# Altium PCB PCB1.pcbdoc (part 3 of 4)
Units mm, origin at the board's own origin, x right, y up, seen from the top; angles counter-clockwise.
Board outline 94.87 x 122.94 mm, 4 copper layers (Top Layer, Inner1, Inner2, Bottom Layer); 129 components, 127 nets, 713 pads, 345 vias.
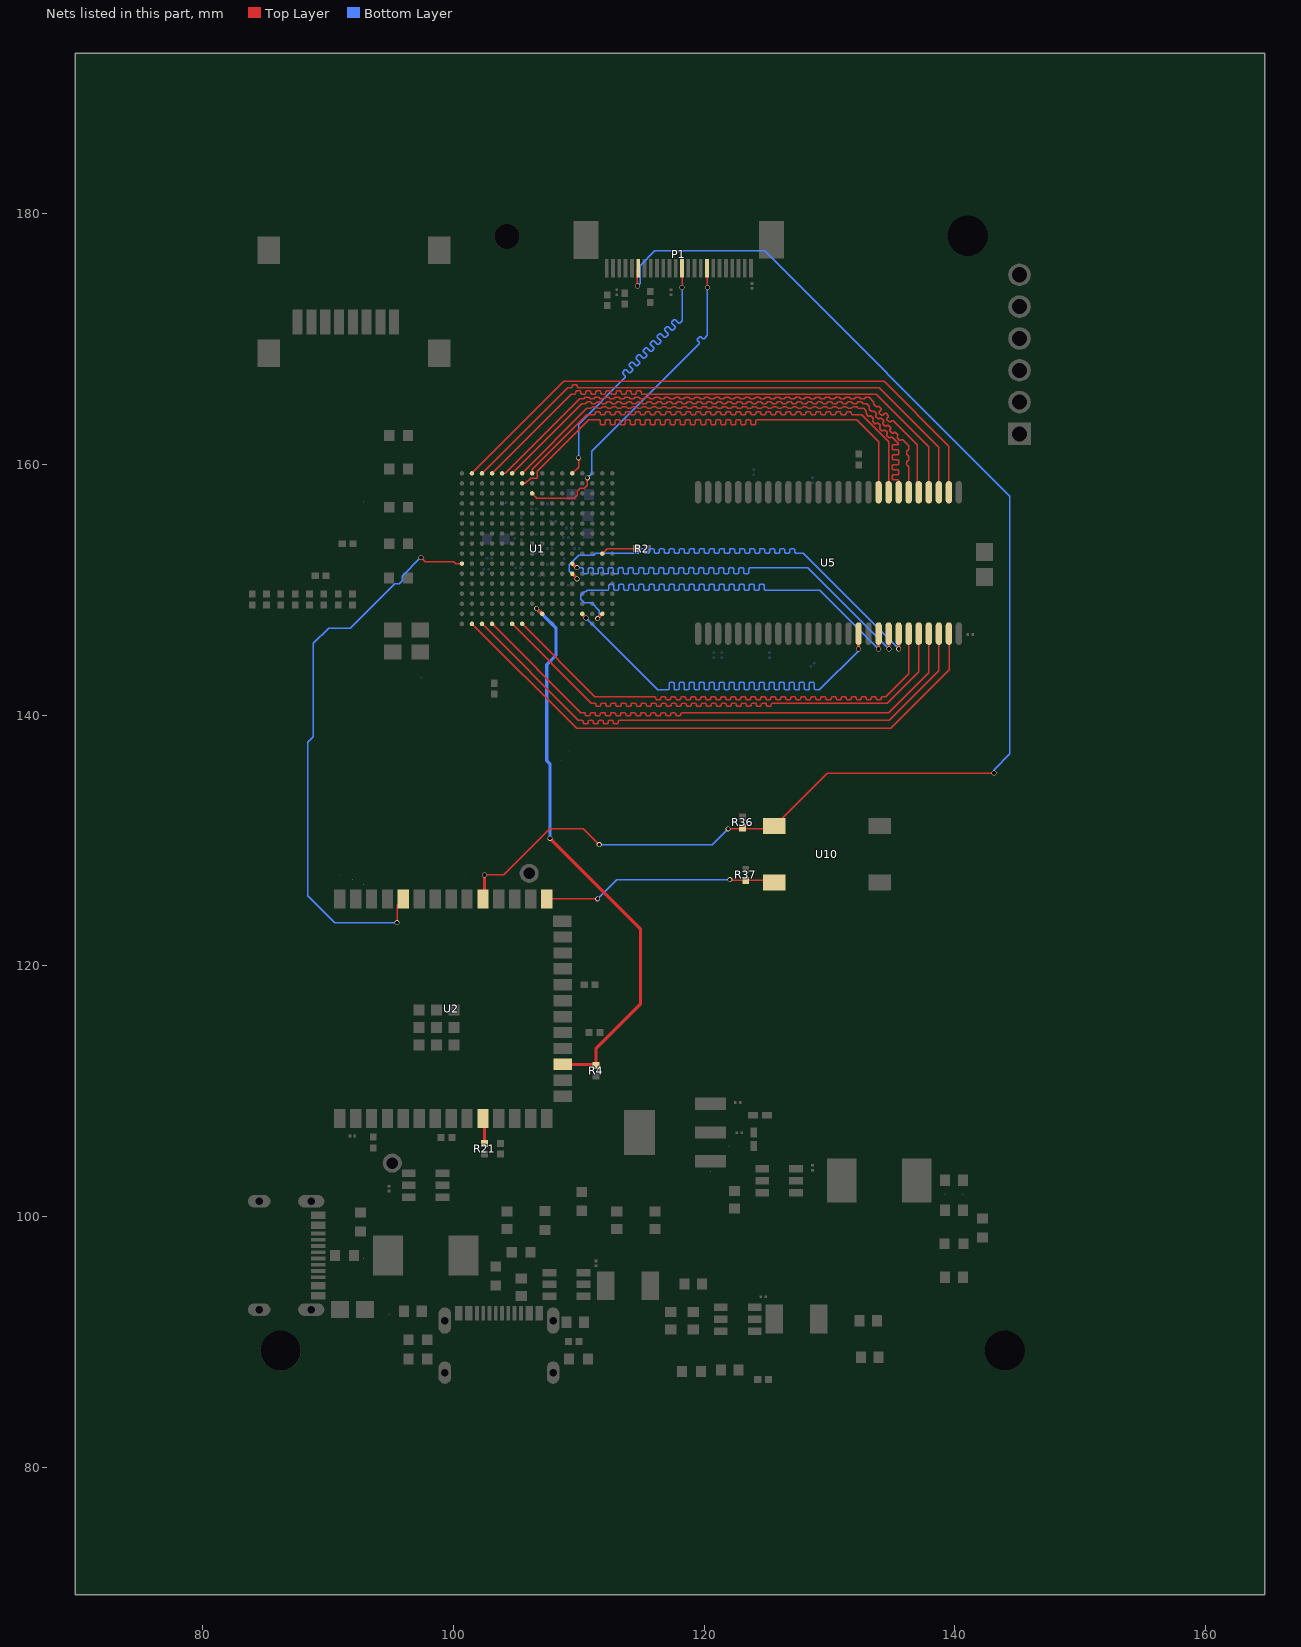
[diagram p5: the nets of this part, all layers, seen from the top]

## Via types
v1: diameter 0.4, hole 0.3, Top Layer to Bottom Layer, 308 vias
v2: diameter 1, hole 0.5, Top Layer to Bottom Layer, 35 vias
v3: diameter 0.5, hole 0.3, Top Layer to Bottom Layer, 2 vias

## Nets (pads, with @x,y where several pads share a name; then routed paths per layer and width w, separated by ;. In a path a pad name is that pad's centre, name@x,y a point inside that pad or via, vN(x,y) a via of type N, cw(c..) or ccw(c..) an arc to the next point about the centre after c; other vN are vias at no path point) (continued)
MCLK: P1.13 U1.A12 | length 27.1
  Top Layer w0.1: U1.A12@109.48,159.289 109.982,159.791 v1(109.982,160.528) ; v1(118.237,174.117) P1.13@118.237,175.655
  Bottom Layer w0.1: v1(109.982,160.528) 109.982,163.195 113.727,166.94 113.727,167.04 113.496,167.271 113.496,167.371 113.679,167.554 113.779,167.554 114.01,167.323 114.11,167.323 114.293,167.506 114.293,167.606 114.012,167.887 114.012,167.987 114.195,168.17 114.295,168.17 114.576,167.889 114.676,167.889 114.858,168.071 114.858,168.171 114.577,168.452 114.577,168.552 114.76,168.735 114.86,168.735 115.141,168.454 115.241,168.454 115.424,168.637 115.424,168.737 115.143,169.018 115.143,169.118 115.326,169.301 115.426,169.301 115.707,169.02 115.807,169.02 115.99,169.203 115.99,169.303 115.709,169.584 115.709,169.684 115.892,169.867 115.992,169.867 116.273,169.586 116.373,169.586 116.555,169.768 116.555,169.868 116.274,170.149 116.274,170.249 116.457,170.432 116.557,170.432 116.838,170.151 116.938,170.151 117.121,170.334 117.121,170.434 116.84,170.715 116.84,170.815 117.023,170.998 117.123,170.998 117.404,170.717 117.504,170.717 117.687,170.9 117.687,171 117.406,171.281 117.406,171.381 117.589,171.564 117.689,171.564 117.97,171.283 118.07,171.283 118.237,171.45 v1(118.237,174.117)
PCLK: P1.17 U1.C8 | length 27
  Top Layer w0.1: U1.C8@106.28,157.689 106.662,157.307 109.638,157.307 109.862,157.531 109.862,157.847 110.122,158.107 110.438,158.107 110.662,158.331 110.662,158.647 110.68,158.665 v1(110.68,158.937) ; P1.17@120.237,175.656 120.269,175.624 v1(120.269,174.117)
  Bottom Layer w0.1: v1(110.68,158.937) 111.019,159.276 111.019,161.057 119.609,169.647 119.609,169.747 119.455,169.901 119.455,170.001 119.637,170.183 119.737,170.183 119.891,170.029 119.991,170.029 120.269,170.307 v1(120.269,174.117)
PROGRAM: R37.1 U2.27 U10.3 | length 18.9
  Top Layer w0.1: U2.27@107.437,125.336 111.493,125.336 v1(111.506,125.349) ; v1(122.047,126.873) 122.099,126.821 R37.1@123.317,126.821 125.428,126.821 U10.3@125.594,126.655
  Bottom Layer w0.1: v1(111.506,125.349) 113.03,126.873 v1(122.047,126.873)
PROGRAMN: pad.55@107.442,136.377 R4.2 U1.R9 U2.17 | length 45.1
  Top Layer w0.254: v1(106.643,148.5) 106.669,148.5 U1.R9@107.08,148.089 ; v1(107.696,130.175) 114.935,122.936 114.935,116.984 111.379,113.428 R4.2@111.379,112.066 111.304,112.141 U2.17@108.844,112.141
  Bottom Layer w0.254: v1(106.643,148.5) 108.175,146.968 108.175,144.758 107.442,144.025 pad.55@107.442,136.377 107.696,136.123 v1(107.696,130.175)
RESET: P1.6 R36.1 U2.31 U10.1 | length 110.8
  Top Layer w0.1: v1(102.484,127.254) 104.013,127.254 107.696,130.937 110.363,130.937 v1(111.633,129.667) ; v1(114.681,174.244) 114.681,175.599 P1.6@114.738,175.655 ; v1(121.92,130.937) 125.376,130.937 U10.1@125.594,131.155 129.821,135.382 v1(143.129,135.382)
  Top Layer w0.254: U2.31@102.484,125.336 v1(102.484,127.254)
  Bottom Layer w0.1: v1(111.633,129.667) 120.65,129.667 v1(121.92,130.937) ; v1(114.681,174.244) 114.907,174.47 114.907,175.867 116.078,177.038 124.841,177.038 144.399,157.48 144.399,136.906 143.129,135.636 v1(143.129,135.382)
RX: U1.K1 U2.36 | length 45.5
  Top Layer w0.1: v1(95.504,123.444) 95.504,124.833 U2.36@96.007,125.336 ; v1(97.41,152.582) 97.738,152.254 100.037,152.254 100.202,152.089 U1.K1@100.68,152.089
  Bottom Layer w0.1: v1(95.504,123.444) 90.551,123.444 88.392,125.603 88.392,137.831 88.832,138.271 88.832,145.728 90.043,146.939 91.767,146.939 95.302,150.474 95.671,150.474 95.906,150.709 95.906,151.078 v1(97.41,152.582)
SCL: R21.1 U2.10 | length 1.9
  Top Layer w0.254: U2.10@102.484,107.836 102.489,107.831 R21.1@102.489,105.918
SD_A0: U1.T6 U5.23 | length 45.3
  Top Layer w0.1: U1.T6@104.68,147.289 110.999,140.97 111.299,140.97 111.37,140.899 111.37,140.787 111.44,140.716 111.699,140.716 111.77,140.787 111.77,140.899 111.84,140.97 112.099,140.97 112.17,140.899 112.17,140.787 112.24,140.716 112.499,140.716 112.57,140.787 112.57,140.899 112.64,140.97 112.899,140.97 112.97,140.899 112.97,140.787 113.04,140.716 113.299,140.716 113.37,140.787 113.37,140.899 113.44,140.97 113.699,140.97 113.77,140.899 113.77,140.787 113.84,140.716 114.099,140.716 114.17,140.787 114.17,140.899 114.24,140.97 114.499,140.97 114.57,140.899 114.57,140.787 114.64,140.716 114.899,140.716 114.97,140.787 114.97,140.899 115.04,140.97 115.299,140.97 115.37,140.899 115.37,140.787 115.44,140.716 115.699,140.716 115.77,140.787 115.77,140.899 115.84,140.97 116.099,140.97 116.17,140.899 116.17,140.787 116.24,140.716 116.499,140.716 116.57,140.787 116.57,140.899 116.64,140.97 116.899,140.97 116.97,140.899 116.97,140.787 117.04,140.716 117.299,140.716 117.37,140.787 117.37,140.899 117.44,140.97 117.699,140.97 117.77,140.899 117.77,140.787 117.84,140.716 118.099,140.716 118.17,140.787 118.17,140.899 118.24,140.97 118.499,140.97 118.57,140.899 118.57,140.787 118.64,140.716 118.899,140.716 118.97,140.787 118.97,140.899 119.04,140.97 119.299,140.97 119.37,140.899 119.37,140.787 119.44,140.716 119.699,140.716 119.77,140.787 119.77,140.899 119.84,140.97 120.099,140.97 120.17,140.899 120.17,140.787 120.24,140.716 120.499,140.716 120.57,140.787 120.57,140.899 120.64,140.97 120.899,140.97 120.97,140.899 120.97,140.787 121.04,140.716 121.299,140.716 121.37,140.787 121.37,140.899 121.44,140.97 121.699,140.97 121.77,140.899 121.77,140.787 121.84,140.716 122.099,140.716 122.17,140.787 122.17,140.899 122.24,140.97 122.499,140.97 122.57,140.899 122.57,140.787 122.64,140.716 122.899,140.716 122.97,140.787 122.97,140.899 123.04,140.97 123.299,140.97 123.37,140.899 123.37,140.787 123.44,140.716 123.699,140.716 123.77,140.787 123.77,140.899 123.84,140.97 124.099,140.97 124.17,140.899 124.17,140.787 124.24,140.716 124.499,140.716 124.57,140.787 124.57,140.899 124.64,140.97 124.899,140.97 124.97,140.899 124.97,140.787 125.04,140.716 125.299,140.716 125.37,140.787 125.37,140.899 125.44,140.97 134.62,140.97 137.121,143.471 U5.23@137.121,146.504
SD_A1: U1.T4 U5.24 | length 45.6
  Top Layer w0.1: U1.T4@103.08,147.289 110.161,140.208 110.461,140.208 110.532,140.137 110.532,140.025 110.602,139.954 110.861,139.954 110.932,140.025 110.932,140.137 111.002,140.208 111.261,140.208 111.332,140.137 111.332,140.025 111.402,139.954 111.661,139.954 111.732,140.025 111.732,140.137 111.802,140.208 112.061,140.208 112.132,140.137 112.132,140.025 112.202,139.954 112.461,139.954 112.532,140.025 112.532,140.137 112.602,140.208 112.861,140.208 112.932,140.137 112.932,140.025 113.002,139.954 113.261,139.954 113.332,140.025 113.332,140.137 113.402,140.208 113.661,140.208 113.732,140.137 113.732,140.025 113.802,139.954 114.061,139.954 114.132,140.025 114.132,140.137 114.202,140.208 114.461,140.208 114.532,140.137 114.532,140.025 114.602,139.954 114.861,139.954 114.932,140.025 114.932,140.137 115.002,140.208 115.261,140.208 115.332,140.137 115.332,140.025 115.402,139.954 115.661,139.954 115.732,140.025 115.732,140.137 115.802,140.208 116.061,140.208 116.132,140.137 116.132,140.025 116.202,139.954 116.461,139.954 116.532,140.025 116.532,140.137 116.602,140.208 116.861,140.208 116.932,140.137 116.932,140.025 117.002,139.954 117.261,139.954 117.332,140.025 117.332,140.137 117.402,140.208 117.661,140.208 117.732,140.137 117.732,140.025 117.802,139.954 118.061,139.954 118.132,140.025 118.132,140.137 118.202,140.208 134.747,140.208 137.922,143.383 U5.24@137.922,146.503
SD_A2: U1.T3 U5.25 | length 45.9
  Top Layer w0.1: U1.T3@102.28,147.289 109.959,139.61 110.282,139.61 110.353,139.539 110.353,139.39 110.423,139.319 110.682,139.319 110.753,139.39 110.753,139.539 110.823,139.61 111.082,139.61 111.153,139.539 111.153,139.39 111.223,139.319 111.482,139.319 111.553,139.39 111.553,139.539 111.623,139.61 111.882,139.61 111.953,139.539 111.953,139.39 112.023,139.319 112.282,139.319 112.353,139.39 112.353,139.539 112.423,139.61 112.682,139.61 112.753,139.539 112.753,139.39 112.823,139.319 113.082,139.319 113.153,139.39 113.153,139.539 113.223,139.61 134.784,139.61 138.721,143.547 U5.25@138.721,146.504
SD_A3: U1.T2 U5.26 | length 46.4
  Top Layer w0.1: U1.T2@101.48,147.289 109.831,138.938 134.874,138.938 139.573,143.637 139.573,146.452 U5.26@139.521,146.504
SD_A4: U1.A2 U5.29 | length 46.9
  Top Layer w0.1: U1.A2@101.48,159.289 108.815,166.624 134.366,166.624 139.521,161.469 U5.29@139.521,157.788
SD_A5: U1.A3 U5.30 | length 45.2
  Top Layer w0.1: U1.A3@102.28,159.289 109.107,166.116 109.407,166.116 109.478,166.187 109.478,166.299 109.548,166.37 109.807,166.37 109.878,166.299 109.878,166.187 109.948,166.116 133.985,166.116 138.721,161.38 U5.30@138.721,157.788
SD_A6: U1.A4 U5.31 | length 45.2
  Top Layer w0.1: U1.A4@103.08,159.289 109.399,165.608 109.699,165.608 109.77,165.679 109.77,165.791 109.84,165.862 110.099,165.862 110.17,165.791 110.17,165.679 110.24,165.608 110.499,165.608 110.57,165.679 110.57,165.791 110.64,165.862 110.899,165.862 110.97,165.791 110.97,165.679 111.04,165.608 111.299,165.608 111.37,165.679 111.37,165.791 111.44,165.862 111.699,165.862 111.77,165.791 111.77,165.679 111.84,165.608 112.099,165.608 112.17,165.679 112.17,165.791 112.24,165.862 112.499,165.862 112.57,165.791 112.57,165.679 112.64,165.608 112.899,165.608 112.97,165.679 112.97,165.791 113.04,165.862 113.299,165.862 113.37,165.791 113.37,165.679 113.44,165.608 113.699,165.608 113.77,165.679 113.77,165.791 113.84,165.862 114.099,165.862 114.17,165.791 114.17,165.679 114.24,165.608 114.499,165.608 114.57,165.679 114.57,165.791 114.64,165.862 114.899,165.862 114.97,165.791 114.97,165.679 115.04,165.608 133.731,165.608 137.921,161.418 U5.31@137.921,157.788
SD_A7: U1.A5 U5.32 | length 45.1
  Top Layer w0.1: U1.A5@103.88,159.289 104.14,159.289 110.078,165.227 110.378,165.227 110.505,165.354 110.778,165.354 110.905,165.227 111.178,165.227 111.305,165.354 111.578,165.354 111.705,165.227 111.978,165.227 112.105,165.354 112.378,165.354 112.505,165.227 112.778,165.227 112.905,165.354 113.178,165.354 113.305,165.227 113.578,165.227 113.705,165.354 113.978,165.354 114.105,165.227 114.378,165.227 114.505,165.354 114.778,165.354 114.905,165.227 115.178,165.227 115.305,165.354 115.578,165.354 115.705,165.227 115.978,165.227 116.105,165.354 116.378,165.354 116.505,165.227 116.778,165.227 116.905,165.354 117.178,165.354 117.305,165.227 117.578,165.227 117.705,165.354 117.978,165.354 118.105,165.227 118.378,165.227 118.505,165.354 118.778,165.354 118.905,165.227 119.178,165.227 119.305,165.354 119.578,165.354 119.705,165.227 119.978,165.227 120.105,165.354 120.378,165.354 120.505,165.227 120.778,165.227 120.905,165.354 121.178,165.354 121.305,165.227 121.578,165.227 121.705,165.354 121.978,165.354 122.105,165.227 122.378,165.227 122.505,165.354 122.778,165.354 122.905,165.227 123.178,165.227 123.305,165.354 123.578,165.354 123.705,165.227 123.978,165.227 124.105,165.354 124.378,165.354 124.505,165.227 124.778,165.227 124.905,165.354 125.178,165.354 125.305,165.227 125.578,165.227 125.705,165.354 125.978,165.354 126.105,165.227 126.378,165.227 126.505,165.354 126.778,165.354 126.905,165.227 127.178,165.227 127.305,165.354 127.578,165.354 127.705,165.227 127.978,165.227 128.105,165.354 128.378,165.354 128.505,165.227 128.778,165.227 128.905,165.354 129.178,165.354 129.305,165.227 129.578,165.227 129.705,165.354 129.978,165.354 130.105,165.227 130.378,165.227 130.505,165.354 130.778,165.354 130.905,165.227 131.178,165.227 131.305,165.354 131.578,165.354 131.705,165.227 131.978,165.227 132.105,165.354 132.378,165.354 132.505,165.227 132.778,165.227 132.905,165.354 133.178,165.354 133.55,164.982 133.55,164.803 133.733,164.62 133.833,164.62 133.845,164.632 133.945,164.632 134.128,164.449 134.128,164.349 133.974,164.195 133.974,164.095 134.156,163.912 134.256,163.912 134.411,164.066 134.511,164.066 134.694,163.883 134.694,163.783 134.588,163.678 134.588,163.578 134.771,163.395 134.871,163.395 134.976,163.501 135.076,163.501 136.994,161.583 136.994,157.915 U5.32@137.121,157.788
SD_A8: U1.A6 U5.33 | length 44.4
  Top Layer w0.1: U1.A6@104.68,159.289 110.237,164.846 110.537,164.846 110.608,164.917 110.608,164.927 110.678,164.998 110.937,164.998 111.008,164.927 111.008,164.917 111.078,164.846 111.337,164.846 111.408,164.917 111.408,164.927 111.478,164.998 111.737,164.998 111.808,164.927 111.808,164.917 111.878,164.846 112.137,164.846 112.208,164.917 112.208,164.927 112.278,164.998 112.537,164.998 112.608,164.927 112.608,164.917 112.678,164.846 112.937,164.846 113.008,164.917 113.008,164.927 113.078,164.998 113.337,164.998 113.408,164.927 113.408,164.917 113.478,164.846 113.737,164.846 113.808,164.917 113.808,164.927 113.878,164.998 114.137,164.998 114.208,164.927 114.208,164.917 114.278,164.846 114.537,164.846 114.608,164.917 114.608,164.927 114.678,164.998 114.937,164.998 115.008,164.927 115.008,164.917 115.078,164.846 115.337,164.846 115.408,164.917 115.408,164.927 115.478,164.998 115.737,164.998 115.808,164.927 115.808,164.917 115.878,164.846 116.137,164.846 116.208,164.917 116.208,164.927 116.278,164.998 116.537,164.998 116.608,164.927 116.608,164.917 116.678,164.846 116.937,164.846 117.008,164.917 117.008,164.927 117.078,164.998 117.337,164.998 117.408,164.927 117.408,164.917 117.478,164.846 117.737,164.846 117.808,164.917 117.808,164.927 117.878,164.998 118.137,164.998 118.208,164.927 118.208,164.917 118.278,164.846 118.537,164.846 118.608,164.917 118.608,164.927 118.678,164.998 118.937,164.998 119.008,164.927 119.008,164.917 119.078,164.846 119.337,164.846 119.408,164.917 119.408,164.927 119.478,164.998 119.737,164.998 119.808,164.927 119.808,164.917 119.878,164.846 120.137,164.846 120.208,164.917 120.208,164.927 120.278,164.998 120.537,164.998 120.608,164.927 120.608,164.917 120.678,164.846 120.937,164.846 121.008,164.917 121.008,164.927 121.078,164.998 121.337,164.998 121.408,164.927 121.408,164.917 121.478,164.846 121.737,164.846 121.808,164.917 121.808,164.927 121.878,164.998 122.137,164.998 122.208,164.927 122.208,164.917 122.278,164.846 122.537,164.846 122.608,164.917 122.608,164.927 122.678,164.998 122.937,164.998 123.008,164.927 123.008,164.917 123.078,164.846 123.337,164.846 123.408,164.917 123.408,164.927 123.478,164.998 123.737,164.998 123.808,164.927 123.808,164.917 123.878,164.846 124.137,164.846 124.208,164.917 124.208,164.927 124.278,164.998 124.537,164.998 124.608,164.927 124.608,164.917 124.678,164.846 124.937,164.846 125.008,164.917 125.008,164.927 125.078,164.998 125.337,164.998 125.408,164.927 125.408,164.917 125.478,164.846 125.737,164.846 125.808,164.917 125.808,164.927 125.878,164.998 126.137,164.998 126.208,164.927 126.208,164.917 126.278,164.846 126.537,164.846 126.608,164.917 126.608,164.927 126.678,164.998 126.937,164.998 127.008,164.927 127.008,164.917 127.078,164.846 127.337,164.846 127.408,164.917 127.408,164.927 127.478,164.998 127.737,164.998 127.808,164.927 127.808,164.917 127.878,164.846 128.137,164.846 128.208,164.917 128.208,164.927 128.278,164.998 128.537,164.998 128.608,164.927 128.608,164.917 128.678,164.846 128.937,164.846 129.008,164.917 129.008,164.927 129.078,164.998 129.337,164.998 129.408,164.927 129.408,164.917 129.478,164.846 129.737,164.846 129.808,164.917 129.808,164.927 129.878,164.998 130.137,164.998 130.208,164.927 130.208,164.917 130.278,164.846 130.537,164.846 130.608,164.917 130.608,164.927 130.678,164.998 130.937,164.998 131.008,164.927 131.008,164.917 131.078,164.846 131.337,164.846 131.408,164.917 131.408,164.927 131.478,164.998 131.737,164.998 131.808,164.927 131.808,164.917 131.878,164.846 132.137,164.846 132.208,164.917 132.208,164.927 132.278,164.998 132.537,164.998 132.608,164.927 132.608,164.917 132.678,164.846 132.969,164.846 133.181,164.634 133.181,164.534 133.169,164.522 133.169,164.422 133.352,164.239 133.452,164.239 133.464,164.251 133.564,164.251 133.747,164.068 133.747,163.968 133.691,163.913 133.691,163.813 133.874,163.63 133.974,163.63 134.03,163.685 134.13,163.685 134.313,163.502 134.313,163.402 134.257,163.347 134.257,163.247 134.44,163.064 134.54,163.064 134.595,163.12 134.695,163.12 134.878,162.937 134.878,162.837 134.823,162.781 134.823,162.681 135.006,162.499 135.106,162.499 135.161,162.554 135.261,162.554 135.444,162.371 135.444,162.271 135.397,162.225 135.397,162.125 135.58,161.942 135.68,161.942 135.727,161.988 135.827,161.988 136.321,161.494 136.321,161.194 136.25,161.123 136.233,161.123 136.162,161.053 136.162,160.794 136.233,160.723 136.25,160.723 136.321,160.653 136.321,160.353 136.25,160.282 136.233,160.282 136.162,160.211 136.162,159.953 136.233,159.882 136.25,159.882 136.321,159.811 U5.33@136.321,157.788
SD_A9: U1.A7 U5.34 | length 45.4
  Top Layer w0.1: U1.A7@105.48,159.289 110.656,164.465 110.956,164.465 111.027,164.536 111.027,164.546 111.098,164.617 111.356,164.617 111.427,164.546 111.427,164.536 111.498,164.465 111.756,164.465 111.827,164.536 111.827,164.546 111.898,164.617 112.156,164.617 112.227,164.546 112.227,164.536 112.298,164.465 112.556,164.465 112.627,164.536 112.627,164.546 112.698,164.617 112.956,164.617 113.027,164.546 113.027,164.536 113.098,164.465 113.356,164.465 113.427,164.536 113.427,164.546 113.498,164.617 113.756,164.617 113.827,164.546 113.827,164.536 113.898,164.465 114.156,164.465 114.227,164.536 114.227,164.546 114.298,164.617 114.556,164.617 114.627,164.546 114.627,164.536 114.698,164.465 114.956,164.465 115.027,164.536 115.027,164.546 115.098,164.617 115.356,164.617 115.427,164.546 115.427,164.536 115.498,164.465 115.756,164.465 115.827,164.536 115.827,164.546 115.898,164.617 116.156,164.617 116.227,164.546 116.227,164.536 116.298,164.465 116.556,164.465 116.627,164.536 116.627,164.546 116.698,164.617 116.956,164.617 117.027,164.546 117.027,164.536 117.098,164.465 117.356,164.465 117.427,164.536 117.427,164.546 117.498,164.617 117.756,164.617 117.827,164.546 117.827,164.536 117.898,164.465 118.156,164.465 118.227,164.536 118.227,164.546 118.298,164.617 118.556,164.617 118.627,164.546 118.627,164.536 118.698,164.465 118.956,164.465 119.027,164.536 119.027,164.546 119.098,164.617 119.356,164.617 119.427,164.546 119.427,164.536 119.498,164.465 119.756,164.465 119.827,164.536 119.827,164.546 119.898,164.617 120.156,164.617 120.227,164.546 120.227,164.536 120.298,164.465 120.556,164.465 120.627,164.536 120.627,164.546 120.698,164.617 120.956,164.617 121.027,164.546 121.027,164.536 121.098,164.465 121.356,164.465 121.427,164.536 121.427,164.546 121.498,164.617 121.756,164.617 121.827,164.546 121.827,164.536 121.898,164.465 122.156,164.465 122.227,164.536 122.227,164.546 122.298,164.617 122.556,164.617 122.627,164.546 122.627,164.536 122.698,164.465 122.956,164.465 123.027,164.536 123.027,164.546 123.098,164.617 123.356,164.617 123.427,164.546 123.427,164.536 123.498,164.465 123.756,164.465 123.827,164.536 123.827,164.546 123.898,164.617 124.156,164.617 124.227,164.546 124.227,164.536 124.298,164.465 124.556,164.465 124.627,164.536 124.627,164.546 124.698,164.617 124.956,164.617 125.027,164.546 125.027,164.536 125.098,164.465 125.356,164.465 125.427,164.536 125.427,164.546 125.498,164.617 125.756,164.617 125.827,164.546 125.827,164.536 125.898,164.465 126.156,164.465 126.227,164.536 126.227,164.546 126.298,164.617 126.556,164.617 126.627,164.546 126.627,164.536 126.698,164.465 126.956,164.465 127.027,164.536 127.027,164.546 127.098,164.617 127.356,164.617 127.427,164.546 127.427,164.536 127.498,164.465 127.756,164.465 127.827,164.536 127.827,164.546 127.898,164.617 128.156,164.617 128.227,164.546 128.227,164.536 128.298,164.465 128.556,164.465 128.627,164.536 128.627,164.546 128.698,164.617 128.956,164.617 129.027,164.546 129.027,164.536 129.098,164.465 129.356,164.465 129.427,164.536 129.427,164.546 129.498,164.617 129.756,164.617 129.827,164.546 129.827,164.536 129.898,164.465 130.156,164.465 130.227,164.536 130.227,164.546 130.298,164.617 130.556,164.617 130.627,164.546 130.627,164.536 130.698,164.465 130.956,164.465 131.027,164.536 131.027,164.546 131.098,164.617 131.356,164.617 131.427,164.546 131.427,164.536 131.498,164.465 131.756,164.465 131.827,164.536 131.827,164.546 131.898,164.617 132.156,164.617 132.227,164.546 132.227,164.536 132.298,164.465 132.715,164.465 132.927,164.253 132.927,164.153 132.915,164.141 132.915,164.041 133.098,163.858 133.198,163.858 133.21,163.87 133.31,163.87 133.493,163.687 133.493,163.587 133.437,163.532 133.437,163.432 133.62,163.249 133.72,163.249 133.776,163.304 133.876,163.304 134.059,163.121 134.059,163.021 134.003,162.966 134.003,162.866 134.186,162.683 134.286,162.683 134.341,162.739 134.441,162.739 134.624,162.556 134.624,162.456 134.569,162.4 134.569,162.3 134.752,162.118 134.852,162.118 134.907,162.173 135.007,162.173 135.521,161.659 135.521,161.651 135.45,161.58 135.072,161.58 135.001,161.51 135.001,161.251 135.072,161.18 135.45,161.18 135.521,161.11 135.521,160.851 135.45,160.78 135.072,160.78 135.001,160.71 135.001,160.451 135.072,160.38 135.45,160.38 135.521,160.31 135.521,160.051 135.45,159.98 135.072,159.98 135.001,159.91 135.001,159.651 135.072,159.58 135.45,159.58 135.521,159.51 135.521,159.251 135.45,159.18 135.072,159.18 135.001,159.11 135.001,158.851 135.072,158.78 135.45,158.78 135.521,158.71 U5.34@135.521,157.788
SD_A10: U1.T7 U5.22 | length 45.1
  Top Layer w0.1: U1.T7@105.48,147.289 111.291,141.478 116.052,141.478 116.122,141.407 116.122,141.295 116.193,141.224 116.452,141.224 116.522,141.295 116.522,141.407 116.593,141.478 116.852,141.478 116.922,141.407 116.922,141.295 116.993,141.224 117.252,141.224 117.322,141.295 117.322,141.407 117.393,141.478 117.652,141.478 117.722,141.407 117.722,141.295 117.793,141.224 118.052,141.224 118.122,141.295 118.122,141.407 118.193,141.478 118.452,141.478 118.522,141.407 118.522,141.295 118.593,141.224 118.852,141.224 118.922,141.295 118.922,141.407 118.993,141.478 119.252,141.478 119.322,141.407 119.322,141.295 119.393,141.224 119.652,141.224 119.722,141.295 119.722,141.407 119.793,141.478 120.052,141.478 120.122,141.407 120.122,141.295 120.193,141.224 120.452,141.224 120.522,141.295 120.522,141.407 120.593,141.478 120.852,141.478 120.922,141.407 120.922,141.295 120.993,141.224 121.252,141.224 121.322,141.295 121.322,141.407 121.393,141.478 121.652,141.478 121.722,141.407 121.722,141.295 121.793,141.224 122.052,141.224 122.122,141.295 122.122,141.407 122.193,141.478 122.452,141.478 122.522,141.407 122.522,141.295 122.593,141.224 122.852,141.224 122.922,141.295 122.922,141.407 122.993,141.478 123.252,141.478 123.322,141.407 123.322,141.295 123.393,141.224 123.652,141.224 123.722,141.295 123.722,141.407 123.793,141.478 124.052,141.478 124.122,141.407 124.122,141.295 124.193,141.224 124.452,141.224 124.522,141.295 124.522,141.407 124.593,141.478 124.852,141.478 124.922,141.407 124.922,141.295 124.993,141.224 125.252,141.224 125.322,141.295 125.322,141.407 125.393,141.478 125.652,141.478 125.722,141.407 125.722,141.295 125.793,141.224 126.052,141.224 126.122,141.295 126.122,141.407 126.193,141.478 126.452,141.478 126.522,141.407 126.522,141.295 126.593,141.224 126.852,141.224 126.922,141.295 126.922,141.407 126.993,141.478 127.252,141.478 127.322,141.407 127.322,141.295 127.393,141.224 127.652,141.224 127.722,141.295 127.722,141.407 127.793,141.478 128.052,141.478 128.122,141.407 128.122,141.295 128.193,141.224 128.452,141.224 128.522,141.295 128.522,141.407 128.593,141.478 128.852,141.478 128.922,141.407 128.922,141.295 128.993,141.224 129.252,141.224 129.322,141.295 129.322,141.407 129.393,141.478 129.652,141.478 129.722,141.407 129.722,141.295 129.793,141.224 130.052,141.224 130.122,141.295 130.122,141.407 130.193,141.478 130.452,141.478 130.522,141.407 130.522,141.295 130.593,141.224 130.852,141.224 130.922,141.295 130.922,141.407 130.993,141.478 131.252,141.478 131.322,141.407 131.322,141.295 131.393,141.224 131.652,141.224 131.722,141.295 131.722,141.407 131.793,141.478 132.052,141.478 132.122,141.407 132.122,141.295 132.193,141.224 132.452,141.224 132.522,141.295 132.522,141.407 132.593,141.478 132.852,141.478 132.922,141.407 132.922,141.295 132.993,141.224 133.252,141.224 133.322,141.295 133.322,141.407 133.393,141.478 133.652,141.478 133.722,141.407 133.722,141.295 133.793,141.224 134.052,141.224 134.122,141.295 134.122,141.407 134.193,141.478 134.493,141.478 136.321,143.306 U5.22@136.321,146.504
SD_A11: U1.A8 U5.35 | length 44.4
  Top Layer w0.1: U1.A8@106.28,159.289 106.28,159.62 110.617,163.957 111.248,163.957 111.319,164.028 111.319,164.14 111.389,164.211 111.648,164.211 111.719,164.14 111.719,164.028 111.789,163.957 112.048,163.957 112.119,164.028 112.119,164.14 112.189,164.211 112.448,164.211 112.519,164.14 112.519,164.028 112.589,163.957 112.848,163.957 112.919,164.028 112.919,164.14 112.989,164.211 113.248,164.211 113.319,164.14 113.319,164.028 113.389,163.957 113.648,163.957 113.719,164.028 113.719,164.14 113.789,164.211 114.048,164.211 114.119,164.14 114.119,164.028 114.189,163.957 114.448,163.957 114.519,164.028 114.519,164.14 114.589,164.211 114.848,164.211 114.919,164.14 114.919,164.028 114.989,163.957 115.248,163.957 115.319,164.028 115.319,164.14 115.389,164.211 115.648,164.211 115.719,164.14 115.719,164.028 115.789,163.957 116.048,163.957 116.119,164.028 116.119,164.14 116.189,164.211 116.448,164.211 116.519,164.14 116.519,164.028 116.589,163.957 116.848,163.957 116.919,164.028 116.919,164.14 116.989,164.211 117.248,164.211 117.319,164.14 117.319,164.028 117.389,163.957 117.648,163.957 117.719,164.028 117.719,164.14 117.789,164.211 118.048,164.211 118.119,164.14 118.119,164.028 118.189,163.957 118.448,163.957 118.519,164.028 118.519,164.14 118.589,164.211 118.848,164.211 118.919,164.14 118.919,164.028 118.989,163.957 119.248,163.957 119.319,164.028 119.319,164.14 119.389,164.211 119.648,164.211 119.719,164.14 119.719,164.028 119.789,163.957 120.048,163.957 120.119,164.028 120.119,164.14 120.189,164.211 120.448,164.211 120.519,164.14 120.519,164.028 120.589,163.957 120.848,163.957 120.919,164.028 120.919,164.14 120.989,164.211 121.248,164.211 121.319,164.14 121.319,164.028 121.389,163.957 121.648,163.957 121.719,164.028 121.719,164.14 121.789,164.211 122.048,164.211 122.119,164.14 122.119,164.028 122.189,163.957 122.448,163.957 122.519,164.028 122.519,164.14 122.589,164.211 122.848,164.211 122.919,164.14 122.919,164.028 122.989,163.957 123.248,163.957 123.319,164.028 123.319,164.14 123.389,164.211 123.648,164.211 123.719,164.14 123.719,164.028 123.789,163.957 124.048,163.957 124.119,164.028 124.119,164.14 124.189,164.211 124.448,164.211 124.519,164.14 124.519,164.028 124.589,163.957 124.848,163.957 124.919,164.028 124.919,164.14 124.989,164.211 125.248,164.211 125.319,164.14 125.319,164.028 125.389,163.957 125.648,163.957 125.719,164.028 125.719,164.14 125.789,164.211 126.048,164.211 126.119,164.14 126.119,164.028 126.189,163.957 126.448,163.957 126.519,164.028 126.519,164.14 126.589,164.211 126.848,164.211 126.919,164.14 126.919,164.028 126.989,163.957 127.248,163.957 127.319,164.028 127.319,164.14 127.389,164.211 127.648,164.211 127.719,164.14 127.719,164.028 127.789,163.957 128.048,163.957 128.119,164.028 128.119,164.14 128.189,164.211 128.448,164.211 128.519,164.14 128.519,164.028 128.589,163.957 128.848,163.957 128.919,164.028 128.919,164.14 128.989,164.211 129.248,164.211 129.319,164.14 129.319,164.028 129.389,163.957 129.648,163.957 129.719,164.028 129.719,164.14 129.789,164.211 130.048,164.211 130.119,164.14 130.119,164.028 130.189,163.957 130.448,163.957 130.519,164.028 130.519,164.14 130.589,164.211 130.848,164.211 130.919,164.14 130.919,164.028 130.989,163.957 131.248,163.957 131.319,164.028 131.319,164.14 131.389,164.211 131.648,164.211 131.719,164.14 131.719,164.028 131.789,163.957 132.588,163.957 134.721,161.824 U5.35@134.721,157.788
SD_A12: U1.B7 U5.36 | length 45.1
  Top Layer w0.1: U1.B7@105.48,158.489 105.74,158.489 106.158,158.907 106.673,158.907 106.698,158.932 106.698,159.447 110.8,163.549 111.64,163.549 111.711,163.478 111.711,163.239 111.781,163.168 112.04,163.168 112.111,163.239 112.111,163.478 112.181,163.549 112.44,163.549 112.511,163.478 112.511,163.239 112.581,163.168 112.84,163.168 112.911,163.239 112.911,163.478 112.981,163.549 113.24,163.549 113.311,163.478 113.311,163.239 113.381,163.168 113.64,163.168 113.711,163.239 113.711,163.478 113.781,163.549 114.04,163.549 114.111,163.478 114.111,163.239 114.181,163.168 114.44,163.168 114.511,163.239 114.511,163.478 114.581,163.549 114.84,163.549 114.911,163.478 114.911,163.239 114.981,163.168 115.24,163.168 115.311,163.239 115.311,163.478 115.381,163.549 115.64,163.549 115.711,163.478 115.711,163.239 115.781,163.168 116.04,163.168 116.111,163.239 116.111,163.478 116.181,163.549 116.44,163.549 116.511,163.478 116.511,163.239 116.581,163.168 116.84,163.168 116.911,163.239 116.911,163.478 116.981,163.549 117.24,163.549 117.311,163.478 117.311,163.239 117.381,163.168 117.64,163.168 117.711,163.239 117.711,163.478 117.781,163.549 118.04,163.549 118.111,163.478 118.111,163.239 118.181,163.168 118.44,163.168 118.511,163.239 118.511,163.478 118.581,163.549 118.84,163.549 118.911,163.478 118.911,163.239 118.981,163.168 119.24,163.168 119.311,163.239 119.311,163.478 119.381,163.549 119.64,163.549 119.711,163.478 119.711,163.239 119.781,163.168 120.04,163.168 120.111,163.239 120.111,163.478 120.181,163.549 120.44,163.549 120.511,163.478 120.511,163.239 120.581,163.168 120.84,163.168 120.911,163.239 120.911,163.478 120.981,163.549 121.24,163.549 121.311,163.478 121.311,163.239 121.381,163.168 121.64,163.168 121.711,163.239 121.711,163.478 121.781,163.549 122.04,163.549 122.111,163.478 122.111,163.239 122.181,163.168 122.44,163.168 122.511,163.239 122.511,163.478 122.581,163.549 122.84,163.549 122.911,163.478 122.911,163.239 122.981,163.168 123.24,163.168 123.311,163.239 123.311,163.478 123.381,163.549 123.64,163.549 123.711,163.478 123.711,163.239 123.781,163.168 124.04,163.168 124.111,163.239 124.111,163.478 124.181,163.549 132.18,163.549 133.921,161.808 U5.36@133.921,157.788
SD_BA0: U1.K12 U5.20 | length 43.4
  Top Layer w0.254: U1.K12@109.48,152.089 109.806,151.763 v1(109.853,151.763) ; U5.20@134.721,146.504 134.747,146.478 v1(134.747,145.288)
  Bottom Layer w0.1: v1(109.853,151.763) 110.294,151.763 110.365,151.693 110.365,151.337 110.436,151.266 110.694,151.266 110.765,151.337 110.765,151.693 110.836,151.763 111.094,151.763 111.165,151.693 111.165,151.337 111.236,151.266 111.494,151.266 111.565,151.337 111.565,151.693 111.636,151.763 111.894,151.763 111.965,151.693 111.965,151.337 112.036,151.266 112.294,151.266 112.365,151.337 112.365,151.693 112.436,151.763 112.694,151.763 112.765,151.693 112.765,151.337 112.836,151.266 113.094,151.266 113.165,151.337 113.165,151.693 113.236,151.763 113.494,151.763 113.565,151.693 113.565,151.337 113.636,151.266 113.894,151.266 113.965,151.337 113.965,151.693 114.036,151.763 114.294,151.763 114.365,151.693 114.365,151.337 114.436,151.266 114.694,151.266 114.765,151.337 114.765,151.693 114.836,151.763 115.094,151.763 115.165,151.693 115.165,151.337 115.236,151.266 115.494,151.266 115.565,151.337 115.565,151.693 115.636,151.763 115.894,151.763 115.965,151.693 115.965,151.337 116.036,151.266 116.294,151.266 116.365,151.337 116.365,151.693 116.436,151.763 116.694,151.763 116.765,151.693 116.765,151.337 116.836,151.266 117.094,151.266 117.165,151.337 117.165,151.693 117.236,151.763 117.494,151.763 117.565,151.693 117.565,151.337 117.636,151.266 117.894,151.266 117.965,151.337 117.965,151.693 118.036,151.763 118.294,151.763 118.365,151.693 118.365,151.337 118.436,151.266 118.694,151.266 118.765,151.337 118.765,151.693 118.836,151.763 119.094,151.763 119.165,151.693 119.165,151.337 119.236,151.266 119.494,151.266 119.565,151.337 119.565,151.693 119.636,151.763 119.894,151.763 119.965,151.693 119.965,151.337 120.036,151.266 120.294,151.266 120.365,151.337 120.365,151.693 120.436,151.763 120.694,151.763 120.765,151.693 120.765,151.337 120.836,151.266 121.094,151.266 121.165,151.337 121.165,151.693 121.236,151.763 121.494,151.763 121.565,151.693 121.565,151.337 121.636,151.266 121.894,151.266 121.965,151.337 121.965,151.693 122.036,151.763 122.294,151.763 122.365,151.693 122.365,151.337 122.436,151.266 122.694,151.266 122.765,151.337 122.765,151.693 122.836,151.763 123.094,151.763 123.165,151.693 123.165,151.337 123.236,151.266 123.494,151.266 123.565,151.337 123.565,151.693 123.636,151.763 128.272,151.763 v1(134.747,145.288)
SD_BA1: U1.L12 U5.21 | length 42.5
  Top Layer w0.254: U1.L12@109.48,151.289 109.855,150.914 v1(109.855,150.876) ; v1(135.521,145.288) U5.21@135.521,146.504
  Bottom Layer w0.1: v1(109.855,150.876) 109.251,151.48 109.251,152.013 109.992,152.753 111.184,152.753 111.339,152.908 114.754,152.908 114.825,152.979 114.825,153.218 114.896,153.289 115.154,153.289 115.225,153.218 115.225,152.979 115.296,152.908 115.554,152.908 115.625,152.979 115.625,153.218 115.696,153.289 115.954,153.289 116.025,153.218 116.025,152.979 116.096,152.908 116.354,152.908 116.425,152.979 116.425,153.218 116.496,153.289 116.754,153.289 116.825,153.218 116.825,152.979 116.896,152.908 117.154,152.908 117.225,152.979 117.225,153.218 117.296,153.289 117.554,153.289 117.625,153.218 117.625,152.979 117.696,152.908 117.954,152.908 118.025,152.979 118.025,153.218 118.096,153.289 118.354,153.289 118.425,153.218 118.425,152.979 118.496,152.908 118.754,152.908 118.825,152.979 118.825,153.218 118.896,153.289 119.154,153.289 119.225,153.218 119.225,152.979 119.296,152.908 119.554,152.908 119.625,152.979 119.625,153.218 119.696,153.289 119.954,153.289 120.025,153.218 120.025,152.979 120.096,152.908 120.354,152.908 120.425,152.979 120.425,153.218 120.496,153.289 120.754,153.289 120.825,153.218 120.825,152.979 120.896,152.908 121.154,152.908 121.225,152.979 121.225,153.218 121.296,153.289 121.554,153.289 121.625,153.218 121.625,152.979 121.696,152.908 121.954,152.908 122.025,152.979 122.025,153.218 122.096,153.289 122.354,153.289 122.425,153.218 122.425,152.979 122.496,152.908 122.754,152.908 122.825,152.979 122.825,153.218 122.896,153.289 123.154,153.289 123.225,153.218 123.225,152.979 123.296,152.908 123.554,152.908 123.625,152.979 123.625,153.218 123.696,153.289 123.954,153.289 124.025,153.218 124.025,152.979 124.096,152.908 124.354,152.908 124.425,152.979 124.425,153.218 124.496,153.289 124.754,153.289 124.825,153.218 124.825,152.979 124.896,152.908 125.154,152.908 125.225,152.979 125.225,153.218 125.296,153.289 125.554,153.289 125.625,153.218 125.625,152.979 125.696,152.908 125.954,152.908 126.025,152.979 126.025,153.218 126.096,153.289 126.354,153.289 126.425,153.218 126.425,152.979 126.496,152.908 126.754,152.908 126.825,152.979 126.825,153.218 126.896,153.289 127.154,153.289 127.225,153.218 127.225,152.979 127.296,152.908 127.901,152.908 v1(135.521,145.288)
SD_CAS_N: U1.R13 U5.17 | length 43.1
  Top Layer w0.254: U1.R13@110.28,148.089 110.28,148.041 v1(110.569,147.753) ; v1(132.321,145.288) U5.17@132.321,146.504
  Bottom Layer w0.1: v1(110.569,147.753) 116.312,142.009 117.132,142.009 117.203,142.08 117.203,142.55 117.273,142.621 117.532,142.621 117.603,142.55 117.603,142.08 117.673,142.009 117.932,142.009 118.003,142.08 118.003,142.55 118.073,142.621 118.332,142.621 118.403,142.55 118.403,142.08 118.473,142.009 118.732,142.009 118.803,142.08 118.803,142.55 118.873,142.621 119.132,142.621 119.203,142.55 119.203,142.08 119.273,142.009 119.532,142.009 119.603,142.08 119.603,142.55 119.673,142.621 119.932,142.621 120.003,142.55 120.003,142.08 120.073,142.009 120.332,142.009 120.403,142.08 120.403,142.55 120.473,142.621 120.732,142.621 120.803,142.55 120.803,142.08 120.873,142.009 121.132,142.009 121.203,142.08 121.203,142.55 121.273,142.621 121.532,142.621 121.603,142.55 121.603,142.08 121.673,142.009 121.932,142.009 122.003,142.08 122.003,142.55 122.073,142.621 122.332,142.621 122.403,142.55 122.403,142.08 122.473,142.009 122.732,142.009 122.803,142.08 122.803,142.55 122.873,142.621 123.132,142.621 123.203,142.55 123.203,142.08 123.273,142.009 123.532,142.009 123.603,142.08 123.603,142.55 123.673,142.621 123.932,142.621 124.003,142.55 124.003,142.08 124.073,142.009 124.332,142.009 124.403,142.08 124.403,142.55 124.473,142.621 124.732,142.621 124.803,142.55 124.803,142.08 124.873,142.009 125.132,142.009 125.203,142.08 125.203,142.55 125.273,142.621 125.532,142.621 125.603,142.55 125.603,142.08 125.673,142.009 125.932,142.009 126.003,142.08 126.003,142.55 126.073,142.621 126.332,142.621 126.403,142.55 126.403,142.08 126.473,142.009 126.732,142.009 126.803,142.08 126.803,142.55 126.873,142.621 127.132,142.621 127.203,142.55 127.203,142.08 127.273,142.009 127.532,142.009 127.603,142.08 127.603,142.55 127.673,142.621 127.932,142.621 128.003,142.55 128.003,142.08 128.073,142.009 128.332,142.009 128.403,142.08 128.403,142.55 128.473,142.621 128.732,142.621 128.803,142.55 128.803,142.08 128.873,142.009 129.173,142.009 132.321,145.157 v1(132.321,145.288)
SD_CLK: R2.2 U1.J15 | length 2.9
  Top Layer w0.1: U1.J15@111.88,152.889 112.28,153.289 R2.2@114.629,153.289
SD_CS_N: U1.R15 U5.19 | length 43
  Top Layer w0.254: v1(111.506,147.701) 111.88,148.075 U1.R15@111.88,148.089 ; v1(133.921,145.288) U5.19@133.921,146.504
  Bottom Layer w0.1: v1(111.506,147.701) 111.633,147.701 111.633,148.336 111.019,148.95 110.45,148.95 110.138,149.262 110.138,149.55 110.419,149.831 110.546,149.831 110.673,149.958 112.333,149.958 112.403,150.029 112.403,150.358 112.474,150.429 112.733,150.429 112.803,150.358 112.803,150.029 112.874,149.958 113.133,149.958 113.203,150.029 113.203,150.358 113.274,150.429 113.533,150.429 113.603,150.358 113.603,150.029 113.674,149.958 113.933,149.958 114.003,150.029 114.003,150.358 114.074,150.429 114.333,150.429 114.403,150.358 114.403,150.029 114.474,149.958 114.733,149.958 114.803,150.029 114.803,150.358 114.874,150.429 115.133,150.429 115.203,150.358 115.203,150.029 115.274,149.958 115.533,149.958 115.603,150.029 115.603,150.358 115.674,150.429 115.933,150.429 116.003,150.358 116.003,150.029 116.074,149.958 116.333,149.958 116.403,150.029 116.403,150.358 116.474,150.429 116.733,150.429 116.803,150.358 116.803,150.029 116.874,149.958 117.133,149.958 117.203,150.029 117.203,150.358 117.274,150.429 117.533,150.429 117.603,150.358 117.603,150.029 117.674,149.958 117.933,149.958 118.003,150.029 118.003,150.358 118.074,150.429 118.333,150.429 118.403,150.358 118.403,150.029 118.474,149.958 118.733,149.958 118.803,150.029 118.803,150.358 118.874,150.429 119.133,150.429 119.203,150.358 119.203,150.029 119.274,149.958 119.533,149.958 119.603,150.029 119.603,150.358 119.674,150.429 119.933,150.429 120.003,150.358 120.003,150.029 120.074,149.958 120.333,149.958 120.403,150.029 120.403,150.358 120.474,150.429 120.733,150.429 120.803,150.358 120.803,150.029 120.874,149.958 121.133,149.958 121.203,150.029 121.203,150.358 121.274,150.429 121.533,150.429 121.603,150.358 121.603,150.029 121.674,149.958 121.933,149.958 122.003,150.029 122.003,150.358 122.074,150.429 122.333,150.429 122.403,150.358 122.403,150.029 122.474,149.958 122.733,149.958 122.803,150.029 122.803,150.358 122.874,150.429 123.133,150.429 123.203,150.358 123.203,150.029 123.274,149.958 123.533,149.958 123.603,150.029 123.603,150.358 123.674,150.429 123.933,150.429 124.003,150.358 124.003,150.029 124.074,149.958 124.333,149.958 124.403,150.029 124.403,150.358 124.474,150.429 124.733,150.429 124.803,150.358 124.803,150.029 124.874,149.958 129.23,149.958 133.773,145.415 133.794,145.415 v1(133.921,145.288)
